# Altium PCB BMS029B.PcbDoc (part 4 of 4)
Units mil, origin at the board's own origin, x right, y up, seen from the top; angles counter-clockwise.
Board outline 4950 x 4000 mil, 4 copper layers (Layer 1 - Top Layer, Layer 2 - GND, Layer 3 - Signal, Layer 4 - Bottom Layer), stack 61.4 mil thick; 370 components, 202 nets, 969 pads, 408 vias.
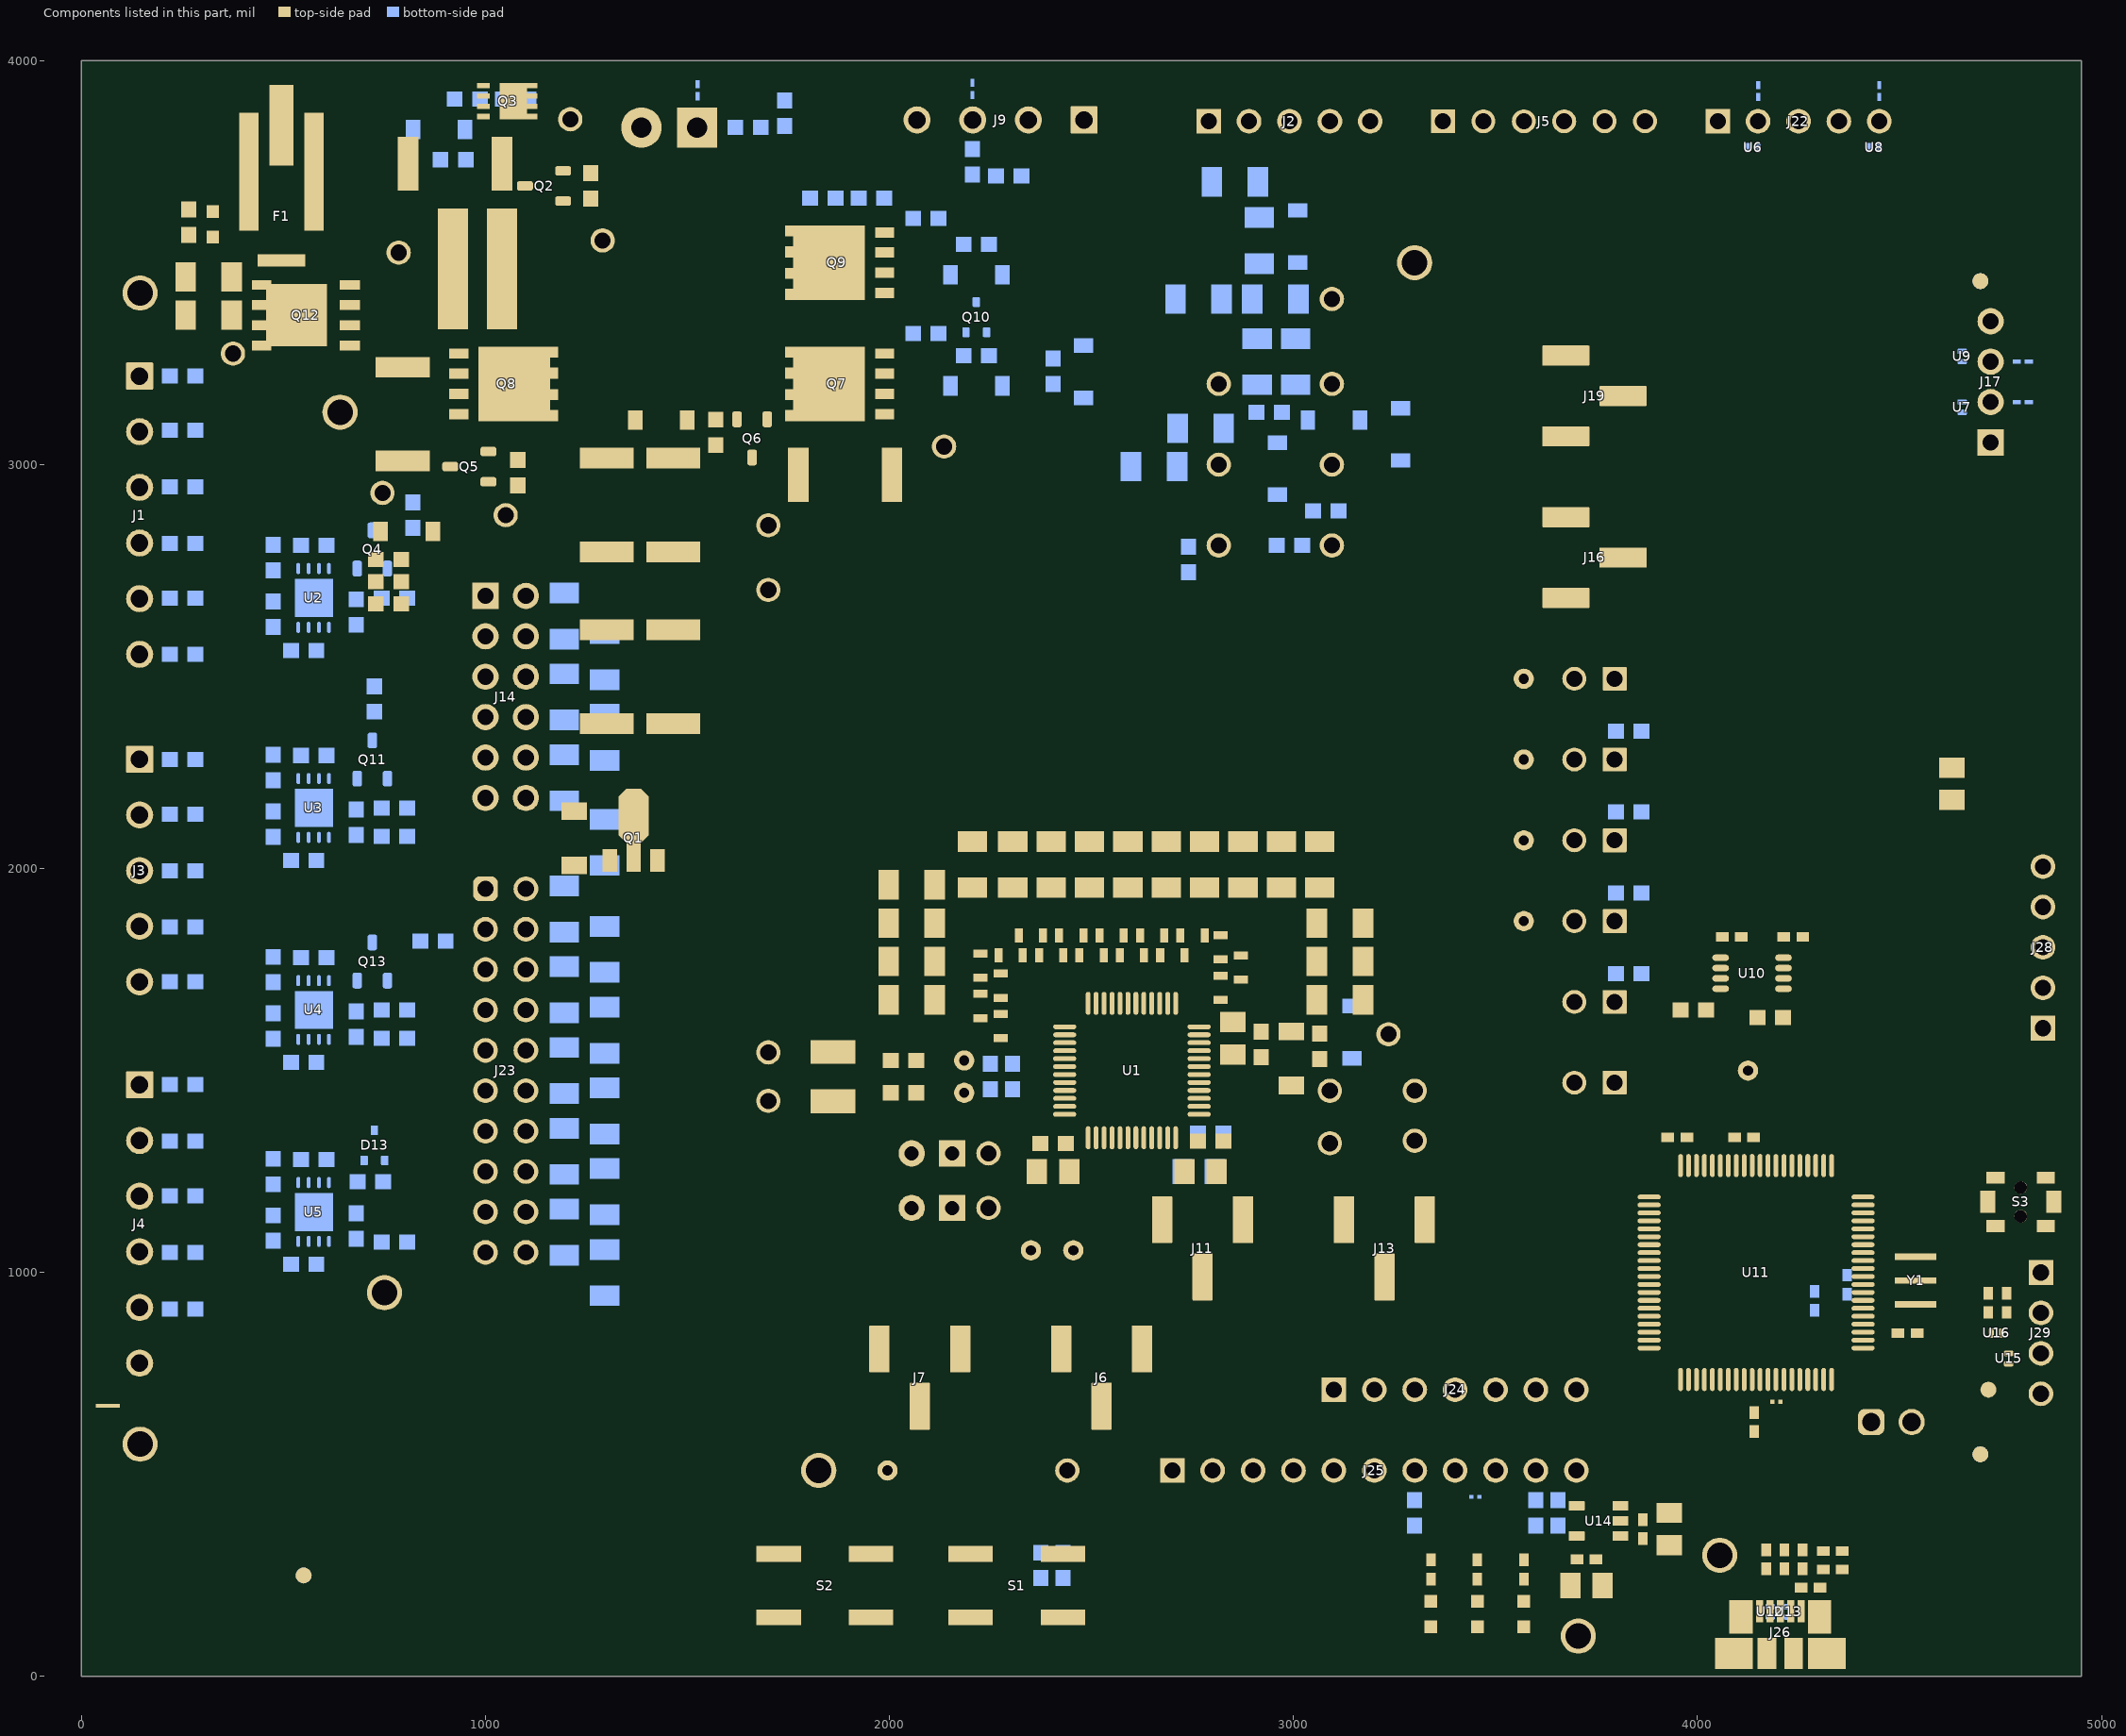
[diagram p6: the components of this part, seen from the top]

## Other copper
Layer 1 - Top Layer:
  pour cut-out: 1435,1924.51 1435.49,1925 1475,1925 1475,1935 1435,1935
  region net NetF1_2: 505,3580 610,3475 610,3285 565,3240 350,3240 305,3285 305,3395 320,3410 400,3410 415,3425 415,3530 440,3555 460,3555 485,3580
  region net NetQ5_3: 950,2960 935,2945 820,2945 785,2980 725,2980 710,2995 710,3070 730,3090 845,3090 865,3070 865,3045 885,3025 935,3025 950,3010
  region net NetD2_1: 1405,3135 1475,3065 1515,3065 1535,3045 1535,2905 1510,2880 1230,2880 1205,2905 1205,3065 1275,3135
  region net CD: 980,3605 980,3080 980,2986 1093.5,2986 1133.37,3025.87 1168.75,3061.25 1177.5,3070 1262.5,3155 1410,3155 1480,3085 1645,3085 1660,3100 1660,3135 1680,3155 1715,3155 1735,3135 1735,3100 1745,3090 1925,3090 1940,3105 1940,3600 1935,3605 1110,3605 1080,3635 1000,3635 980,3615
  region net NetC71_1: 1210,2465 1180,2435 1180,2100 1210,2070 1330,2070 1345,2055 1345,1990 1390,1990 1390,2055 1405.01,2070.01 1425.01,2070.01 1470,2115 1470,2210 1585,2325 1585,2435 1555,2465
  region net NetR6_1: 1370,2515 1340,2485 1210,2485 1180,2515 1180,2830 1210,2860 1370,2860
  region net NetR5_1: 1395,2515 1425,2485 1555,2485 1585,2515 1585,2830 1555,2860 1395,2860
  pour cut-out: 694.71,3070 694.71,3225 705,3225 715,3215 715,3085 700,3070
  region net QGND: 4027,1711 4081.82,1711 4085,1707.82 4085,1702 4027,1702
  region net PGND: 4610,2232 4603,2225 4577.42,2225 4577.42,2260 4682.58,2260 4682.58,2225 4655,2225 4648,2232
  region net QGND: 4610,2188 4603,2195 4577.42,2195 4577.42,2160 4682.58,2160 4682.58,2195 4655,2195 4648,2188
  pour cut-out: 4899.65,1085.2 4899.65,1264.8 4700.35,1264.8 4700.35,1085.2
  pour cut-out: 3054.49,755.51 3054.49,845 3085,845 3085,755.51
  pour cut-out: 3731.81,372.81 3731.81,386.81 3743,398 3783,398 3783,409 3726,409 3720,403 3720,372.81
  pour cut-out: 4675,3105 4675,3405 4775,3405 4775,3105
  pour cut-out: 3825,700 4475,700 4475,1325 3825,1325
  pour cut-out: 2650,460 3745,460 3745,560 2650,560
  pour cut-out: 2035,510 2050,510 2160,620 2160,825 2085,825 2085,600 2035,550
  pour cut-out: 2425,1325 2775,1325 2775,1675 2425,1675
  pour cut-out: 3131.5,1912.32 3098.5,1912.32 3098.5,1621.95 3131.5,1621.74
  pour cut-out: 2153.58,2026.5 2153.58,1993.5 3116.42,1993.5 3116.42,2026.5
  pour cut-out: 2038.5,1623.58 2071.5,1623.58 2071.5,2011.42 2038.5,2011.42
  pour cut-out: 950,2125 1150,2125 1150,2725 950,2725
  region net VSS: 55,690 45,700 20,700 20,640 45,640 55,650
  region net VSS: 690,3410 690,3115 660,3085 620,3085 590,3115 590,3235 635,3280 635,3410
  region net QGND: 4600,2185 4590,2175 4590,2125 4670,2125 4670,2175 4660,2185
  region net PGND: 4660,2235 4670,2245 4670,2295 4590,2295 4590,2245 4600,2235
  region net VSS: 2785,1215 2865,1215 2890,1240 2890,1305 2850,1345 2805,1345 2805,1305 2785,1285
  region net VSS: 2900,1555 2900,1490 2950,1440 3030,1440 3030,1490 2965,1555
  region net BAT-: 75,475 135,415 1550,415 1920,785 1920,1420 1940,1440 1940,1450 1920,1470 1649.99,1469.99 1500,1320 1500,965 1370,835 150,835 75,760
  region net PGND: 1920,1500 1940,1520 1940,1530 1920,1550 1920,2020 2705,2805 2705,3850 2630,3925 2360,3925 2285,3850 2285,2980 1500,2195 1500,1650 1650,1500
  region net 16P: 60,3145 30,3175 30,3625 30,3940 60,3970 455,3970 485,3940 485,3718.75 485,3610 450,3575 390,3575 355,3610 340,3610 240,3610 215,3585 215,3330 300,3245 300,3175 270,3145
  region net FBAT: 505,3940 535,3970 990,3970 1015,3945 1015,3885 1009,3879 969,3879 960,3870 960,3160 955,3155 780,3155 710,3225 710,3485 690,3505 610,3505 505,3610
  region net NetQ2_3: 1000,3675 1125,3675 1125,3820 1110,3835 1085,3835 1035,3835 980,3780 980,3695
  region net CPACK+: 1035,3875 1035,3855 1130,3855 1158,3827 1158,3700 1290,3700 1350,3640 1725,3640 1760,3675 1760,3890 1725,3925 1470,3925 1425,3970 1060,3970 1035,3945
  region net NetQ6_3: 1645,2985 1735,2895 1860,2895 1880,2915 1880,3025 1862,3043 1645,3043
  region net PACK+: 2265,3850 2265,2990 2170,2895 1920,2895 1900,2915 1900,3040 1960,3100 1960,3235 1965,3240 2020,3240 2035,3255 2035,3305 2005,3335 1975,3335 1960,3350 1960,3535 1965,3540 2020,3540 2035,3555 2035,3615 2010,3640 1943.5,3640 1900,3683.5 1900,3830 1900,3875 1950,3925 2190,3925
  region net 12P: 100,2650 145,2605 355,2605 770.89,2189.11 770.89,2075 795,2050.89 834.11,2050.89 858.23,2075 858.23,2343.23 651.46,2550 651.46,2650 651.46,2688.54 610,2730 145,2730 100,2685
  region net VSS: 770,2688.7 848.7,2688.7 915,2755 915,2875 860,2875 770,2785
  region net 8P: 560,1930 770,1720 770,1580 795,1555 835,1555 860,1580 860,1920 730,2050 730,2160 690,2200 490,2200 349.45,2059.45 139.45,2059.45 100,2020 100,1970 140,1930
  region net 4P: 140,1390 190,1390 500,1700 625,1700 725,1600 725,1495 860,1360 860,1075 835,1050 795,1050 770,1075 770,1179.37 679.37,1270 135,1270 100,1305 100,1350
  region net QGND: 4488,996 4491,999 4593,999 4601,1007 4617,1007 4617,953 4601,953 4593,961 4491,961 4488,964
  region net VBUS: 4162,134.13 4162,223.64 4135.51,250.13 4135.51,315.13 4090.51,360.13 3790.51,360.13 3785.51,355.13 3785.51,319.49 3894.87,210.13 4134.51,210.13 4145,199.64 4145,134.13
  region net NetJ26_6: 4137,190 4137,106 4147,96 4262,96 4273,107 4273,193 4285,205 4285,230 4290,235 4329.21,235 4370,194.21 4370,18 4043,18 4043,163 4070,190
  region net QGND: 3810,185 3746.46,185 3732,199.46 3732,382 3748,398 3838,398 3845,405 3845,440 3865,460 3955,460 3965,450 3965,380 3957,372 3787,372 3775,360 3775,310 3826,259 3826,201 3825,200
  region net 3.3V: 3721,164 3755,130 3755,80 3720,45 3630,45 3605,70 3605,256.65 3591.65,270 3315,270 3300,285 3300,360 3315,375 3708,375 3721,362
  region net QGND: 4700,700 4720,680 4765,680 4765,730 4700,730
  pour cut-out: 3370.75,92.76 3539.25,92.76 3539.25,100 3370.75,100
  text ".Layer_Name" at 577,-858.49 h60
Layer 2 - GND:
  pour cut-out: 2206.11,3804.68 2270,3804.68 2270,3815 2206.11,3815
  pour cut-out: 2120,3419.51 2180,3419.51 2180,3430 2120,3430
  pour cut-out: 1595,3765 1320,3765 1320,3900 1595,3900
  pour cut-out: 4380,580 4580,580 4580,680 4380,680
  pour cut-out: 4675,3105 4675,3405 4775,3405 4775,3105
  pour cut-out: 950,2125 1150,2125 1150,2725 950,2725
  text ".Layer_Name" at 577,-858.49 h60
Layer 3 - Signal:
  pour cut-out: 3750.14,1447.55 3750,1405 3760,1405 3760,1447.55
  pour cut-out: 935,2725 935,2125 1150,2125 1150,2725
  pour cut-out: 955,1000 955,2000 1210,2000 1210,1000
  pour cut-out: 1590,3765 1320,3765 1320,3900 1590,3900
  pour cut-out: 2206.11,3804.68 2270,3804.68 2270,3815 2206.11,3815
  pour cut-out: 2120,3419.51 2180,3419.51 2180,3430 2120,3430
  pour cut-out: 2305,2084.51 3160,2084.51 3160,2110 2305,2110
  pour cut-out: 4380,580 4580,580 4580,680 4380,680
  pour cut-out: 4895.9,800 4895.9,900 4804.1,900 4804.1,800
  pour cut-out: 4768.99,1139.57 4768.99,1210.43 4790,1210.43 4790,1139.57
  pour cut-out: 4675,3105 4675,3405 4775,3405 4775,3105
  text ".Layer_Name" at 577,-858.49 h60
Layer 4 - Bottom Layer:
  pour cut-out: 4396.81,915.63 4396.81,901.81 4380,885 4357.5,885 4357.5,915.63
  pour cut-out: 3184.02,1497.52 3187.91,1497.52 3240.49,1550.1 3240.49,1675 3230.49,1685 3223.01,1692.48 3105.98,1692.48 3105.98,1559.98 3074.51,1528.5 3074.51,1425.49 3100,1400 3150,1400 3184.02,1434.02
  pour cut-out: 2546.5,286.1 2615,286.1 2615,300 2546.5,300
  pour cut-out: 2450.39,400 2450.39,480 2430,480 2430,400
  pour cut-out: 2857.32,3148.58 3052.68,3148.58 3052.68,3180 2857.32,3180
  pour cut-out: 1296.42,647.32 1296.42,2443.58 1265,2475 1125,2475 1100,2450 1100,2386.5 1004.1,2290.59 1004.1,795 1050,749.1 1193.58,749.1 1193.58,647.32
  pour cut-out: 316.18,1291.3 316.18,1083 304.34,1083 300,1083 300,1291.3
  pour cut-out: 316.18,1961.3 316.18,1753.7 300,1753.7 300,1961.3
  pour cut-out: 316.18,2636.3 316.18,2563.7 299,2563.7 299,2636.3
  pour cut-out: 316.18,2563.7 316.18,2636.3 301.89,2636.3 301.89,2563.7
  pour cut-out: 316.18,3186.3 316.18,2978.7 293,2978.7 293,3186.3
  pour cut-out: 1320.69,3834.5 1320.69,3753 1333,3753 1333,3834.5
  pour cut-out: 3240,3800 3254.51,3800 3254.51,3808 3240,3808
  region net PGND: 4132,3806.67 4129.4,3809.27 4126.27,3809.27 4125,3808 4125,3762 4126,3761 4129,3761 4132,3764
  region net PGND: 4432,3806.67 4429.4,3809.27 4426.27,3809.27 4425,3808 4425,3762 4426,3761 4429,3761 4432,3764
  region net PGND: 4675,3273 4675,3284 4636,3284 4630,3278 4630,3276 4633,3273
  region net PGND: 4675,3137 4675,3125 4637,3125 4630,3132 4630,3134 4633,3137
  pour cut-out: 4900.9,1559.49 4884,1559.49 4884,1905 4900.9,1905
  region net QGND: 4157,164 4250,164 4250,172 4157,172
  pour cut-out: 2654.49,464.1 2654.49,555.9 3735,555.9 3735,464.1
  pour cut-out: 950,2125 1150,2125 1150,2725 950,2725
  region net VSS: 2780,1285 2890,1285 2890,1240 2875,1225 2840,1225 2830,1215 2780,1215
  region net PGND: 4435,3900 4420,3900 4405,3915 4405,3965 4495,3965 4495,3915 4480,3900 4465,3900 4465,3925 4460,3930 4440,3930 4435,3925
  region net PGND: 4135,3900 4120,3900 4105,3915 4105,3965 4195,3965 4195,3915 4180,3900 4165,3900 4165,3925 4160,3930 4140,3930 4135,3925
  region net PGND: 4780,3130 4795,3115 4865,3115 4865,3295 4795,3295 4780,3280 4780,3270 4805,3270 4810,3265 4810,3245 4805,3240 4780,3240 4780,3170 4805,3170 4810,3165 4810,3145 4805,3140 4780,3140
  region net FBAT: 950,3890 945,3885 920,3885 910,3875 910,3735 798.03,3735 798.03,3928.03 815,3945 935,3945 950,3930
  region net NetC29_1: 965,3885 1065,3885 1065,3930 1050,3945 980,3945 965,3930
  region net CPACK+: 1085,3880 1100,3865 1155,3865 1155,3945 1100,3945 1085,3930
  region net CPACK+: 1640,3800 1620,3780 1475,3780 1465,3790 1465,3875 1475,3885 1515,3885 1520,3890 1520,3922 1530,3922 1530,3890 1535,3885 1620,3885 1640,3865
  region net NetC34_2: 1660,3810 1670,3800 1755,3800 1765,3810 1765,3855 1755,3865 1670,3865 1660,3855
  region net PGND: 1700,3965 1700,3900 1720,3880 1760,3880 1780,3900 1780,3965
  region net PACK+: 2195,3575 2205,3565 2205,3455 2185,3435 2110,3435 2110,3555 2130,3575
  region net PACK+: 1965,3640 2020,3640 2035,3655 2035,3735 1980,3735 1965,3720
  region net PGND: 1510,3902 1495,3902 1480,3917 1480,3967 1570,3967 1570,3917 1555,3902 1540,3902 1540,3927 1535,3932 1515,3932 1510,3927
  region net PGND: 2190,3905 2175,3905 2160,3920 2160,3970 2250,3970 2250,3920 2235,3905 2220,3905 2220,3930 2215,3935 2195,3935 2190,3930
  region net PACK+: 2200,3925 2200,3900 2170,3870 2170,3760 2240,3760 2240,3870 2210,3900 2210,3925
  region net NetC42_2: 2185,3740 2185,3690 2285,3690 2285,3740
  region net PGND: 2305,3690 2320,3675 2370,3675 2370,3755 2320,3755 2305,3740
  region net PGND: 2450,3125 2530,3125 2530,3205 2450,3205
  region net 12P: 527,2718 527,2622 627,2622 650,2645 765,2645 765,2690 650,2690 622,2718
  region net 8P: 527,2198 527,2102 627,2102 650,2125 765,2125 765,2170 650,2170 622,2198
  region net 4P: 527,1698 527,1602 627,1602 650,1625 765,1625 765,1670 650,1670 622,1698
  region net VSS: 527,1198 527,1102 627,1102 650,1125 700,1125 700,1170 650,1170 622,1198
  pour cut-out: 4245,343.45 4245,365 4230,380 4230,795 4250,815 4325,815 4345,795 4370,795 4385,810 4385,890 4370,905 4345,905 4286,846 4236,846 4200,810 4200,415 4140,355 4140,335 4155,320 4230,320 4245,335
  region net NetC37_1: 1845,3630 1945,3630 1945,3700 1845,3700
  region net FBAT: 1825,3630 1320,3630 1265,3685 1190,3685 1110,3605 890,3605 880,3615 880,3670 890,3680 1065,3680 1155,3770 1300,3770 1370,3700 1815,3700 1825,3690
  pour cut-out: 4675,3105 4675,3405 4775,3405 4775,3105
  region net PACK+: 2205,3065 2235,3035 2625,3035 2635,3025 2635,2960 2625,2950 2200,2950 2175,2950 2115,3010 2095,3030 2095,3230 2165,3300 2165,3340 2175,3350 2195,3350 2205,3340
  region net CD: 1940,3605 1295,3605 1090,3400 1090,3014.75 1122.25,3014.75 1262.5,3155 1420,3155 1450,3125 1940,3125
  pour cut-out: 2625,3050.29 2679.71,3050.29 2680.01,2920 2625,2920
  pour cut-out: 2753.5,3038.58 2795,3038.58 2795,3141.42 2753.5,3141.42
  pour cut-out: 3056.42,3238.5 3056.42,3280 2858.58,3280 2858.58,3238.5
  pour cut-out: 2748.5,3358.58 2790,3358.58 2790,3461.42 2748.5,3461.42
  pour cut-out: 2966.42,3538.5 2966.42,3580 2863.58,3580 2863.58,3538.5
  pour cut-out: 2838.5,3648.58 2880,3648.58 2880,3751.42 2838.5,3751.42
  text ".Layer_Name" at 577,-858.49 h60

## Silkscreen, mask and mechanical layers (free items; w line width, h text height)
Top Overlay:
  text "EXT SPI" at 4115,3920 h75
  text "CPACK+" at 1115,3780 h50
  text "CPACK+" at 1320,3660 h75
  text "TS2" at 3215,3655 h75 r90
  text "PACK+" at 2031.01,3644.5 h75
  text "PACK-" at 2314.71,3644.5 h75
  text "VSS" at 2815,3640 h75 r90
  text "VSS" at 3395,3640 h75 r90
  text "REG1" at 3015,3605 h75 r90
  text "REG2" at 2915,3595 h75 r90
  text "DCHG" at 3695,3585 h75 r90
  text "DDSG" at 3795,3585 h75 r90
  text "Input 6A max" at 2055,3580 h75
  text "REGIN" at 3115,3570 h75 r90
  text "PACK-" at 4075,3565 h75 r90
  text "SPI_CS" at 4175,3540 h75 r90
  text "BAT+" at 45,3510 h75
  text "SPI_CLK" at 4275,3495 h75 r90
  text "DFETOFF" at 3495,3470 h75 r90
  text "CFETOFF" at 3595,3470 h75 r90
  text "SPI_MISO" at 4375,3465 h75 r90
  text "SPI_MOSI" at 4475,3465 h75 r90
  text "FBAT" at 730,3450 h50
  text "CD" at 1260,3435 h50
  text "RST_SHUT" at 3895,3425 h75 r90
  text "GND" at 3230,3320 h75
  text "PACK" at 3035,3290 h50
  text "uC_SCL" at 3865,3245 h75
  text "FUSE" at 405,3220 h50
  text "CELL16" at 316.06,3160 h75
  text "SCL" at 3500,3140 h75
  text "Dg" at 2788.25,3089.94 h50
  text "DSG" at 3050,3090 h50
  text "EXT I2C" at 4660,3080 h75 r90
  text "CELL15" at 316.06,3057.65 h75
  text "uC_SPI_CLK" at 3865,3045 h75
  text "GND" at 570,3000 h75
  text "CELL14" at 316.06,2919.65 h75
  text "PACK+" at 2070,2915 h50
  text "FUSEPIN" at 785,2890 h50
  text "LD" at 2790,2890 h50
  text "PCHG" at 3035,2890 h50
  text "uC_SDA" at 3865,2845 h75
  text "CELL13" at 316.06,2781.65 h75
  text "Pcg" at 1010,2760 h50
  text "SDA" at 3500,2745 h75
  text "Pdg" at 1660,2740 h50
  text "CHG" at 2775,2690 h50
  text "PDSG" at 3040,2690 h50
  text "16" at 860,2650 h75
  text "uC_SPI_MISO_A" at 3865,2645 h75
  text "CELL12" at 316.06,2643.65 h75
  text "Cg" at 1670,2575 h50
  text "15" at 860,2550 h75
  text "CELL11" at 316.06,2505.65 h75
  text "14" at 860,2450 h75
  text "CFETOFF" at 3325,2440 h50
  text "uC_SPI_CS" at 3570,2355 h75
  text "13" at 860,2350 h75
  text "12" at 860,2250 h75
  text "CELL10" at 316.06,2246.65 h75
  text "HDQ" at 3425,2225 h50
  text "Cell simulator" at 1210,2205 h75 r90
  text "HDQ_PU" at 3620,2155 h75
  text "11" at 860,2150 h75
  text "CELL9" at 316.06,2108.65 h75
  text "SDA" at 3435,2030 h50
  text "CELL8" at 316.06,1970.65 h75
  text "SDA_PU" at 3620,1955 h75
  text "10" at 860,1925 h75
  text "SCL" at 3435,1835 h50
  text "CELL7" at 316.06,1832.65 h75
  text "9" at 895,1825 h75
  text "SCL_PU" at 3620,1755 h75
  text "8" at 895,1725 h75
  text "CELL6" at 316.06,1694.65 h75
  text "7" at 895,1625 h75
  text "ALERT_PU" at 3580,1555 h75
  text "BAT" at 3275,1545 h50
  text "6" at 895,1525 h75
  text "SRN" at 2225,1510 h50
  text "CELL5" at 316.06,1435.65 h75
  text "SRP" at 2225,1430 h50
  text "5" at 895,1425 h75
  text "CP1" at 3135,1405 h50
  text "GND" at 3340,1405 h50
  text "BAT-" at 1510,1375 h75
  text "uC_HDQ" at 3610,1355 h75
  text "TS1" at 2205,1335 h50
  text "4" at 895,1325 h75
  text "Input 72V max" at 715,1310 h75 r90
  text "Input 6A max" at 800,1310 h75 r90
  text "CELL4" at 316.06,1297.65 h75
  text "BREG" at 3135,1280 h50
  text "REGIN" at 3340,1280 h50
  text "Cell simulator" at 1210,1265 h75 r90
  text "3" at 895,1225 h75
  text "CELL3" at 316.06,1159.65 h75
  text "2" at 895,1125 h75
  text "ALERT" at 2405,1090 h50
  text "PU" at 2610,1080 h75 r90
  text "PD" at 2990,1080 h75 r90
  text "TS3" at 2205,1040 h50
  text "1" at 900,1025 h75
  text "CELL2" at 316.06,1021.65 h75
  text "uC_HDQ" at 3440,980 h75 r90
  text "REG18" at 2275,945 h50
  text "CELL1" at 316.06,883.65 h75
  text "uC_SPI_MOSI" at 3050,855 h75 r90
  text "GND" at 675,775 h75
  text "HDQ" at 3250,775 h75 r90
  text "PD" at 2290,760 h75 r90
  text "PU" at 2360,760 h75 r90
  text "PD" at 2740,760 h75 r90
  text "EXT" at 1905,755 h75 r90
  text "BAT-" at 316.06,745.65 h75
  text "QGND" at 4595,625 h75
  text "CFETOFF" at 2800,615 h75 r90
  text "TS2" at 2100,475 h75 r90
  text "TS2" at 1955,400 h50
  text "REG1" at 2365,390 h50
  text "VBUS" at 3980,385 h75
  text "GND" at 1755,370 h75
  text "DFETOFF" at 2550,295 h75 r90
  text "BQ76952EVM" at 745,215 h108.27
  text "'.PRJ_Number'.PCB_Rev" at 745,125 h108.27
  text "USB" at 4405,80 h75
  text "3.3V" at 3795,60 h75
  text "WAKE" at 1740,30 h75
  text "RESET" at 2210,30 h75
  text ".Layer_Name" at 577,-858.49 h60
Bottom Overlay:
  text ".Layer_Name" at 577,-858.49 h60
Top Paste:
  text ".Layer_Name" at 577,-858.49 h60
Bottom Paste:
  text ".Layer_Name" at 577,-858.49 h60
Top Solder:
  text ".Layer_Name" at 577,-858.49 h60
  text ".Layer_Name" at 577,-858.49 h60
Bottom Solder:
  text ".Layer_Name" at 577,-858.49 h60
Drill Guide:
  text ".Layer_Name" at 577,-858.49 h60
M1 Board Outline:
  the board outline again, w10
  text ".Layer_Name" at 577,-858.49 h60
M2 Board Dimensions:
  rectangle: 0,-275 125,-150
  rectangle: 125,-400 500,-275
  lines w7: 0,-275 1000,-275 ; 125,-400 125,-150 ; 250,-400 250,-150 ; 500,-400 500,-150 ; 750,-400 750,-150 ; 0,-400 1000,-400 1000,-150 0,-150 0,-400
  text ".Layer_Name" at 577,-858.49 h60
M3 3D STEP Top:
  text ".Layer_Name" at 577,-858.49 h60
M4 3D STEP Bottom:
  text ".Layer_Name" at 577,-858.49 h60
M5 Assembly Top:
  lines w10: -292,-930.17 6308,-930.17 ; -292,-726.83 6310,-726.83 ; -292,-523.5 -292,-1133.5 3713,-1133.5 6310,-1133.5 6310,-523.5 -291.5,-523.5 -291.5,-1133.5 1284,-1133.5 ; 2173,-1133.5 2173,-523.5 ; 3440,-726.83 3440,-523.5 ; 4280,-726.83 4280,-523.5 ; 4902,-1140 4902,-937.17
  text "COMPONENTS MARKED 'DNP' SHOULD NOT BE POPULATED." at 1153.5,-318.5 h60
  text "ASSEMBLY VARIANT:" at 1153,-434 h60
  text ".VariantName" at 2189,-434 h60
  text "PCB VIEWED FROM TOP SIDE" at -228.5,-655.67 h60
  text "BOARD #:" at 2248,-655.67 h60
  text ".PRJ_Number" at 2793.5,-655.67 h60
  text "REV:" at 3638,-655.67 h60
  text ".PCB_Rev" at 3929.5,-655.67 h60
  text "SVN REV:" at 4476,-655.67 h60
  text ".VersionControl_RevNumber" at 4982,-655.67 h60
  text "TID #:" at 2248,-859 h60
  text ".TID" at 2793.5,-859 h60
  text "PLOT NAME =" at -228.5,-1064.34 h60
  text ".plot_File_Name" at 577,-1064.34 h60
  text "GENERATED    :" at 2250,-1064.34 h60
  text ".Print_Date" at 3119.5,-1064.34 h60
  text ".Print_Time" at 3848.5,-1064.34 h60
  text "TEXAS INSTRUMENTS" at 5113,-1064.34 h60
M6 Assembly Bottom:
  lines w10: -292.5,-727.33 6309.5,-727.33 ; -290.5,-930.67 6309.5,-930.67 ; 1115.5,-1140.5 1115.5,-937.67 ; 1737.5,-727.33 1737.5,-524 ; 2577.5,-727.33 2577.5,-524 ; 3844.5,-1134 3844.5,-524 ; 4733.5,-1134 6309,-1134 6309,-524 -292.5,-524 -292.5,-1134 2304.5,-1134 6309.5,-1134 6309.5,-524
  text "COMPONENTS MARKED 'DNP' SHOULD NOT BE POPULATED." at 6102,-318 h60
  text ".VariantName" at 5058,-434 h60
  text "ASSEMBLY VARIANT:" at 6097,-434 h60
  text ".VersionControl_RevNumber" at 1035.5,-656.17 h60
  text "SVN REV:" at 1541.5,-656.17 h60
  text ".PCB_Rev" at 2088,-656.17 h60
  text "REV:" at 2379.5,-656.17 h60
  text ".PRJ_Number" at 3224,-656.17 h60
  text "BOARD #:" at 3769.5,-656.17 h60
  text "PCB VIEWED FROM BOTTOM SIDE" at 6246,-656.17 h60
  text ".TID" at 3224,-859.5 h60
  text "TID #:" at 3769.5,-859.5 h60
  text "TEXAS INSTRUMENTS" at 904.5,-1064.84 h60
  text ".Print_Time" at 2169,-1064.84 h60
  text ".Print_Date" at 2898,-1064.84 h60
  text "GENERATED    :" at 3767.5,-1064.84 h60
  text ".plot_File_Name" at 5440.5,-1064.84 h60
  text "PLOT NAME =" at 6246,-1064.84 h60
M9 Title Sheet:
  drawing of 1178 lines, arcs and shapes, not listed
  text "1" at 739.84,8036.5 h70
  text "2" at 3235.5,8036.5 h70
  text "3" at 5724.84,8036.5 h70
  text "4" at 8231.51,8036.5 h70
  text "5" at 10730.5,8036.5 h70
  text "6" at 13235.5,8036.5 h70
  text "A" at -416.5,6893.5 h70
  text "A" at 14383.5,6893.5 h70
  text "B" at -416.5,4513.5 h70
  text "B" at 14383.5,4513.5 h70
  text "C" at -416.5,2138.5 h70
  text "C" at 14383.5,2138.5 h70
  text "PROJECT TITLE:" at 11343.5,277.5 h45
  text ".PRJ_Title" at 11393.5,144.17 h70
  text "DESIGNED FOR:" at 11343.5,-23.5 h45
  text ".PRJ_Customer" at 11393.5,-163.5 h70
  text "D" at -416.5,-231.5 h70
  text "D" at 14383.5,-231.5 h70
  text "FILE NAME:" at 11343.5,-323.5 h45
  text ".PCB_File_Name_No_Path" at 11393.5,-443.5 h70
  text "Texas Instruments (TI) and/or its licensors do not warrant the accuracy or completeness of this specification" at 6374,-605.34 h45
  text "ENGINEER:" at 11343.5,-613.5 h45
  text "LAYOUT BY:" at 12848.5,-613.5 h45
  text "or any information contained therein. TI and/or its licensors do not warrant that this design will meet" at 6329.01,-718 h45
  text ".PRJ_Engineer" at 11393.5,-768.49 h70
  text "JMM" at 12852,-800 h100
  text "s  o  l  u  t  i  o  n  s" at 13710,-803 h68
  text "the specifications, will be suitable for your application or fit for any particular purpose, or will operate in" at 6329.01,-830.67 h45
  text ".Layer_Name" at 577,-858.49 h60
  text "ALTIUM DESIGNER VERSION:" at 12848.5,-923.5 h45
  text "an implementation. TI and/or its licensors do not warrant that the design is production worthy. You should" at 6329.01,-943.33 h45
  text "completely validate and test your design implementation to confirm the system functionality for your application." at 6374,-1056 h45
  text ".print_Scale" at 11393.5,-1056.83 h70
  text ".Application_BuildNumber" at 12899,-1056.83 h70
  text "1" at 739.84,-1263.5 h70
  text "2" at 3235.5,-1263.5 h70
  text "3" at 5724.84,-1263.5 h70
  text "4" at 8231.51,-1263.5 h70
  text "5" at 10730.5,-1263.5 h70
  text "6" at 13235.5,-1263.5 h70
M10 Fab Notes:
  drawing of 189 lines, arcs and shapes, not listed
  text "DESIGN INFORMATION" at 12382.02,6356.17 h60
  text "MIN. TRACK WIDTH:" at 11737.46,6224.05 h60
  text "8" at 12833.7,6224.05 h60
  text "MIL" at 12988.46,6224.05 h60
  text "MIN. CLEARANCE:" at 11737.46,6099.92 h60
  text "0.2" at 12773.7,6099.93 h60
  text "mm" at 12988.46,6099.92 h60
  text "MIN. VIA PAD SIZE:" at 11737.46,5975.8 h60
  text "20" at 12803.71,5975.8 h60
  text "MIL" at 12988.46,5975.8 h60
  text "0.05mm (2MIL)" at 12432.46,5845.9 h60
  text "MINIMUM ANNULAR RING" at 11408.23,5837.67 h60
  text "EXTERNAL" at 13140.46,5837.67 h60
  text "PER" at 11608.23,5727.55 h60
  text "IPC-D-275 CLASS 2 LEVEL C" at 11828.23,5727.54 h60
  text "MIL, HOLES" at 13316.46,5627.07 h60
  text "+/-" at 12924,5618.48 h60
  text "+/-" at 13778,5618.48 h60
  text "REGISTRATION TOLERANCES:" at 11408.23,5617.42 h60
  text "METAL" at 12608,5617.42 h60
  text "5" at 13184.2,5617.42 h60
  text "3" at 14017.2,5617.42 h60
  text "MIL" at 14133.46,5617.42 h60
  text "HOLE SIZE TOLERANCE (UNLESS OTHERWISE SPECIFIED):" at 11408.23,5519.1 h60
  text "+/-" at 13778,5516.23 h60
  text "3" at 14017.2,5515.17 h60
  text "MIL" at 14133.46,5515.17 h60
  text "MATERIAL:" at 11333.46,5377.52 h60
  text "FR-4 High Tg" at 12319.9,5249 h60
  text "X" at 12175.46,5241.01 h60
  text "FR-408" at 11754.46,5236.49 h60
  text "OTHER" at 13242.46,5236.49 h60
  text "62 MIL (1.6mm) +/-10%" at 12074.56,5093.46 h60
  text "X" at 11954.46,5091.01 h60
  text "THICKNESS:" at 11408.23,5085.24 h60
  text "OTHER" at 13359.46,5085.24 h60
  text "TOLERANCE:" at 11408.23,4946.92 h60
  text "X" at 12256.46,4946.92 h60
  text "ANSI IPC-6012 TYPE 3 CLASS 2" at 12434.48,4946.92 h60
  text "OTHER +/-" at 12434.46,4802.73 h60
  text "BOW & TWIST:" at 11408.23,4657.54 h60
  text "X" at 12256.46,4657.54 h60
  text "ANSI IPC-6012 TYPE 3 CLASS 2" at 12434.48,4657.54 h60
  text "OTHER +/-" at 12434.46,4510.85 h60
  text "DRILLING:" at 11333.46,4380.23 h60
  text "NC_DRILL FILES" at 13094.46,4275.04 h60
  text "REFERENCE:" at 11408.23,4271.1 h60
  text "X" at 12065.46,4271.01 h60
  text "AS SHOWN" at 12243.46,4271.1 h60
  text "X" at 12966.46,4271.1 h60
  text "OTHER" at 13392.46,4128.85 h60
  text "PTH COPPER THICKNESS:" at 11407.91,4125.32 h60
  text "X" at 12547.14,4125.32 h60
  text "20-30 um" at 12675.14,4125.32 h60
  text "BOARD FINISH:" at 11333.46,3977.73 h60
  text "SILKSCREEN:" at 11488.68,3867.6 h60
  text "X" at 12446.46,3867.6 h60
  text "TOP" at 12563.46,3867.6 h60
  text "X" at 12956.46,3867.6 h60
  text "BOTTOM" at 13074.46,3867.6 h60
  text "SILKSCREEN COLOR:" at 11488.68,3712.41 h60
  text "X" at 12445.46,3712.41 h60
  text "WHITE" at 12563.46,3712.41 h60
  text "OTHER" at 13074.46,3712.41 h60
  text "X" at 12576.46,3568.96 h60
  text "GREEN" at 12694.46,3568.96 h60
  text "OTHER" at 13312.46,3568.96 h60
  text "SOLDER RESIST COLOR:" at 11488.68,3562.1 h60
  text "X" at 12576.46,3414.71 h60
  text "MATTE" at 12694.46,3414.71 h60
  text "SEMI-GLOSS" at 13312,3414.07 h60
  text "IMMERSION GOLD (ENIG)" at 12394.46,3241.94 h60
  text "ENEPIG" at 13732,3234.72 h60
  text "SURFACE FINISH:" at 11333.46,3233.72 h60
  text "X" at 12216.46,3233.72 h60
  text "IMM. TIN/SILVER OR EQUIV" at 11663,3096.4 h60
  text "OTHER" at 13094.46,3092.47 h60
  text "ARRAY/PANEL:" at 11333.46,2937.09 h60
  text "CUT AND TRIM PER M1 BOARD OUTLINE" at 12394.46,2928.87 h60
  text "N.C. ROUTE" at 12394.46,2792.9 h60
  text "X" at 13082.46,2792.9 h60
  text "V. SCORE" at 13260.46,2792.9 h60
  text "CERTIFICATION:" at 11333.46,2663.77 h60
  text "MATERIALS AND WORKMANSHIP FOR ALL PCBS" at 12058.46,2663.77 h60
  text "TO MEET OR EXCEED THE REQUIREMENTS OF:" at 12058.46,2569.71 h60
  text "X" at 11695.97,2441.08 h60
  text "ANSI IPC-A-600F CLASS ->" at 11823.96,2441.08 h60
  text "X" at 13471.97,2441.08 h60
  text "2" at 13581.96,2441.08 h60
  text "1" at 13266.96,2439.58 h60
  text "3" at 13935.96,2439.58 h60
  text "X" at 12507.97,2293.39 h60
  text "RoHS" at 12635.96,2293.39 h60
  text "OTHER" at 13280.36,2293.39 h60
  text "PER ORDER" at 13677.42,2293.39 h60
  text "ALL BOARDS MUST MEET OR EXCEED UL94-V0 REQUIREMENTS." at 11361,2139.57 h60
  text "PCB MUST BEAR THE UL94V-0 UL REGISTERED MATERIAL ID NUMBER" at 11361,2023.5 h60
  text "ADDITIONAL REQUIREMENTS:" at 11333.46,1854.08 h60
  text "MICROSECTION:" at 11408.23,1746.95 h60
  text "YES" at 12313.96,1746.95 h60
  text "REQUIRED" at 13175.46,1602.62 h60
  text "BARE BOARD ELEC. TEST:" at 11408.23,1599.76 h60
  text "NONE" at 12713.96,1599.76 h60
  text "X" at 13057.46,1599.76 h60
  text "PER ORDER" at 13767.46,1599.76 h60
  text "XX MIL VIAS REQUIRE NON-CONDUCTIVE FILL AND PLANARIZE" at 11576.38,1394.82 h59
  text "XX MIL VIAS REQUIRE CONDUCTIVE FILL AND PLANARIZE" at 11584.38,1290.84 h60
  text "OUTER XX MIL TRACES REQUIRE 50 OHM SINGLE-ENDED IMPEDANCE" at 11583.39,1127.46 h58
  text "LAYER 2 & 3 (INNER LAYERS) XX MIL WIDE, XX MIL SPACE / TRACES REQUIRE 100 OHM DIFFERENTIAL IMPEDANCE" at 11575.39,891.74 h60
  text ".Layer_Name" at 577,-858.49 h60
M11 Gerber Information:
  lines w10: -292,-930.17 6308,-930.17 ; -292,-726.83 6310,-726.83 ; -292,-523.5 -292,-1133.5 3713,-1133.5 6310,-1133.5 6310,-523.5 -291.5,-523.5 -291.5,-1133.5 1284,-1133.5 ; 2173,-1133.5 2173,-523.5 ; 3440,-726.83 3440,-523.5 ; 4280,-726.83 4280,-523.5 ; 4902,-1140 4902,-937.17
  text "ALL ARTWORK VIEWED FROM TOP SIDE" at -228.5,-655.67 h60
  text "BOARD #:" at 2248,-655.67 h60
  text ".PRJ_Number" at 2793.5,-655.67 h60
  text "REV:" at 3638,-655.67 h60
  text ".PCB_Rev" at 3929.5,-655.67 h60
  text "SVN REV:" at 4476,-655.67 h60
  text ".VersionControl_RevNumber" at 4982,-655.67 h60
  text "LAYER NAME =" at -228.5,-858.49 h60
  text "TID #:" at 2248,-859 h60
  text ".TID" at 2793.5,-859 h60
  text "PLOT NAME =" at -228.5,-1064.34 h60
  text ".plot_File_Name" at 577,-1064.34 h60
  text "GENERATED    :" at 2250,-1064.34 h60
  text ".Print_Date" at 3119.5,-1064.34 h60
  text ".Print_Time" at 3848.5,-1064.34 h60
  text "TEXAS INSTRUMENTS" at 5113,-1064.34 h60
M12 Stackup:
  drawing of 295 lines, arcs and shapes, not listed
  text "Layer" at 9322.5,7842.5 h60
  text "Name" at 9732.41,7842.5 h60
  text "Material" at 11142,7842.5 h60
  text "Thickness" at 12001.77,7842.5 h60
  text "Constant" at 12651.6,7842.5 h60
  text "Board Layer Stack" at 13221.47,7842.5 h60
  text "1" at 9322.5,7722.5 h60
  text "Top Overlay" at 9732.41,7722.5 h60
  text "2" at 9322.5,7602.5 h60
  text "Top Solder" at 9732.41,7602.5 h60
  text "Solder Resist" at 11142,7602.5 h60
  text "0.40mil" at 12001.77,7602.5 h60
  text "3.5" at 12651.6,7602.5 h60
  text "3" at 9322.5,7482.5 h60
  text "Layer 1 - Top Layer" at 9732.41,7482.5 h60
  text "Copper" at 11142,7482.5 h60
  text "2.80mil" at 12001.77,7482.5 h60
  text "4" at 9322.5,7362.5 h60
  text "Dielectric 1" at 9732.41,7362.5 h60
  text "FR-4 High Tg" at 11142,7362.5 h60
  text "6.00mil" at 12001.77,7362.5 h60
  text "4.2" at 12651.6,7362.5 h60
  text "5" at 9322.5,7242.5 h60
  text "Layer 2 - GND" at 9732.41,7242.5 h60
  text "Copper" at 11142,7242.5 h60
  text "1.40mil" at 12001.77,7242.5 h60
  text "6" at 9322.5,7122.5 h60
  text "Dielectric 2" at 9732.41,7122.5 h60
  text "FR-4 High Tg" at 11142,7122.5 h60
  text "41.00mil" at 12001.77,7122.5 h60
  text "4.2" at 12651.6,7122.5 h60
  text "7" at 9322.5,7002.5 h60
  text "Layer 3 - Signal" at 9732.41,7002.5 h60
  text "Copper" at 11142,7002.5 h60
  text "1.40mil" at 12001.77,7002.5 h60
  text "8" at 9322.5,6882.5 h60
  text "Dielectric 3" at 9732.41,6882.5 h60
  text "FR-4 High Tg" at 11142,6882.5 h60
  text "6.00mil" at 12001.77,6882.5 h60
  text "4.2" at 12651.6,6882.5 h60
  text "9" at 9322.5,6762.5 h60
  text "Layer 4 - Bottom Layer" at 9732.41,6762.5 h60
  text "Copper" at 11142,6762.5 h60
  text "2.80mil" at 12001.77,6762.5 h60
  text "10" at 9322.5,6642.5 h60
  text "Bottom Solder" at 9732.41,6642.5 h60
  text "Solder Resist" at 11142,6642.5 h60
  text "0.40mil" at 12001.77,6642.5 h60
  text "3.5" at 12651.6,6642.5 h60
  text "11" at 9322.5,6522.5 h60
  text "Bottom Overlay" at 9732.41,6522.5 h60
  text ".Layer_Name" at 577,-858.49 h60
M13 Component Bodies Top:
  text ".Layer_Name" at 577,-858.49 h60
M14 Component Bodies Bottom:
  text ".Layer_Name" at 577,-858.49 h60
M15 Courtyards Top:
  text ".Layer_Name" at 577,-858.49 h60
M16 Courtyards Bottom:
  text ".Layer_Name" at 577,-858.49 h60
Drill Drawing:
  circle w10: c5270.22,1086.98 r16.58
  circle w10: c5270.22,1086.98 r27.63
  circle w10: c5270.22,216.74 r27.63
  lines w10: 5242.59,313.44 5297.84,313.44 5297.84,368.69 5242.59,368.69 5242.59,313.44 ; 5242.59,451.57 5256.4,451.57 5270.22,437.76 5284.03,451.57 5297.84,451.57 5284.03,465.38 5297.84,479.2 5284.03,479.2 5270.22,493.01 5256.4,479.2 5242.59,479.2 5256.4,465.38 5242.59,451.57 ; 5242.59,686.4 5297.84,686.4 5297.84,741.65 5242.59,741.65 5242.59,686.4 ; 5242.59,810.72 5242.59,824.53 5256.4,838.34 5242.59,852.16 5242.59,865.97 5256.4,865.97 5270.22,852.16 5284.03,865.97 5297.84,865.97 5297.84,852.16 5284.03,838.34 5297.84,824.53 5297.84,810.72 5284.03,810.72 5270.22,824.53 5256.4,810.72 5242.59,810.72 ; 5242.59,935.04 5270.22,948.85 5297.84,935.04 5284.03,962.66 5297.84,990.29 5270.22,976.48 5242.59,990.29 5256.4,962.66 5242.59,935.04 ; 5242.59,1197.49 5256.4,1197.49 5270.22,1183.68 5284.03,1197.49 5297.84,1197.49 5284.03,1211.3 5297.84,1225.12 5284.03,1225.12 5270.22,1238.93 5256.4,1225.12 5242.59,1225.12 5256.4,1211.3 5242.59,1197.49 ; 5242.59,1308 5270.22,1321.81 5297.84,1308 5284.03,1335.62 5297.84,1363.25 5270.22,1349.44 5242.59,1363.25 5256.4,1335.62 5242.59,1308 ; 5242.59,1459.94 5270.22,1432.32 5297.84,1459.94 5270.22,1487.57 5242.59,1459.94 ; 5253.64,457.09 5261.93,457.09 5270.22,448.81 5278.51,457.09 5286.79,457.09 5278.51,465.38 5286.79,473.67 5278.51,473.67 5270.22,481.96 5261.93,473.67 5253.64,473.67 5261.93,465.38 5253.64,457.09 ; 5253.64,697.45 5286.79,697.45 5286.79,730.6 5253.64,730.6 5253.64,697.45 ; 5253.64,1319.05 5270.22,1327.33 5286.79,1319.05 5278.51,1335.62 5286.79,1352.2 5270.22,1343.91 5253.64,1352.2 5261.93,1335.62 5253.64,1319.05
  lines w15: 5192.5,151.82 8959.42,151.82 ; 5192.5,1519.34 8959.42,1519.34 ; 5530.36,27.5 5530.36,1643.66 ; 5831.62,27.5 5831.62,1643.66 ; 6394.89,27.5 6394.89,1643.66 ; 6654.03,27.5 6654.03,1643.66 ; 7029.18,27.5 7029.18,1643.66 ; 8222.16,27.5 8222.16,1643.66 ; 8525.45,27.5 8525.45,1643.66 ; 5192.5,27.5 8959.42,27.5 8959.42,1643.66 5192.5,1643.66 5192.5,27.5
  text "Symbol" at 5267.09,1556.64 h72
  text "Count" at 5567.66,1556.64 h72
  text "Hole Size" at 5868.91,1556.64 h72
  text "Plated" at 6432.18,1556.64 h72
  text "Hole Type" at 6691.32,1556.64 h72
  text "Drill Layer Pair" at 7066.48,1556.64 h72
  text "Via/Pad" at 8259.45,1556.64 h72
  text "Pad Shape" at 8562.75,1556.64 h72
  text "2" at 5567.66,1432.32 h60
  text "31.50mil (0.800mm)" at 5868.91,1432.32 h60
  text "NPTH" at 6432.18,1432.32 h60
  text "Round" at 6691.32,1432.32 h60
  text "Layer 1 - Top Layer - Layer 4 - Bottom Layer" at 7066.48,1432.32 h60
  text "Pad" at 8259.45,1432.32 h60
  text "Rounded" at 8562.75,1432.32 h60
  text "2" at 5567.66,1308 h60
  text "45.28mil (1.150mm)" at 5868.91,1308 h60
  text "PTH" at 6432.18,1308 h60
  text "Round" at 6691.32,1308 h60
  text "Layer 1 - Top Layer - Layer 4 - Bottom Layer" at 7066.48,1308 h60
  text "Pad" at 8259.45,1308 h60
  text "(Mixed)" at 8562.75,1308 h60
  text "2" at 5567.66,1183.68 h60
  text "50.00mil (1.270mm)" at 5868.91,1183.68 h60
  text "PTH" at 6432.18,1183.68 h60
  text "Round" at 6691.32,1183.68 h60
  text "Layer 1 - Top Layer - Layer 4 - Bottom Layer" at 7066.48,1183.68 h60
  text "Pad" at 8259.45,1183.68 h60
  text "(Mixed)" at 8562.75,1183.68 h60
  text "4" at 5567.66,1059.36 h60
  text "35.00mil (0.889mm)" at 5868.91,1059.36 h60
  text "PTH" at 6432.18,1059.36 h60
  text "Round" at 6691.32,1059.36 h60
  text "Layer 1 - Top Layer - Layer 4 - Bottom Layer" at 7066.48,1059.36 h60
  text "Pad" at 8259.45,1059.36 h60
  text "(Mixed)" at 8562.75,1059.36 h60
  text "8" at 5567.66,935.04 h60
  text "40.16mil (1.020mm)" at 5868.91,935.04 h60
  text "PTH" at 6432.18,935.04 h60
  text "Round" at 6691.32,935.04 h60
  text "Layer 1 - Top Layer - Layer 4 - Bottom Layer" at 7066.48,935.04 h60
  text "Pad" at 8259.45,935.04 h60
  text "(Mixed)" at 8562.75,935.04 h60
  text "8" at 5567.66,810.72 h60
  text "63.00mil (1.600mm)" at 5868.91,810.72 h60
  text "PTH" at 6432.18,810.72 h60
  text "Round" at 6691.32,810.72 h60
  text "Layer 1 - Top Layer - Layer 4 - Bottom Layer" at 7066.48,810.72 h60
  text "Pad" at 8259.45,810.72 h60
  text "Rounded" at 8562.75,810.72 h60
  text "10" at 5567.66,686.4 h60
  text "25.00mil (0.635mm)" at 5868.91,686.4 h60
  text "PTH" at 6432.18,686.4 h60
  text "Round" at 6691.32,686.4 h60
  text "Layer 1 - Top Layer - Layer 4 - Bottom Layer" at 7066.48,686.4 h60
  text "Pad" at 8259.45,686.4 h60
  text "Rounded" at 8562.75,686.4 h60
  text "21" at 5567.66,562.08 h60
  text "43.31mil (1.100mm)" at 5868.91,562.08 h60
  text "PTH" at 6432.18,562.08 h60
  text "Round" at 6691.32,562.08 h60
  text "Layer 1 - Top Layer - Layer 4 - Bottom Layer" at 7066.48,562.08 h60
  text "Pad" at 8259.45,562.08 h60
  text "(Mixed)" at 8562.75,562.08 h60
  text "B" at 5241.81,552.09 h55.25
  text "32" at 5567.66,437.76 h60
  text "7.87mil (0.200mm)" at 5868.91,437.76 h60
  text "PTH" at 6432.18,437.76 h60
  text "Round" at 6691.32,437.76 h60
  text "Layer 1 - Top Layer - Layer 4 - Bottom Layer" at 7066.48,437.76 h60
  text "Via" at 8259.45,437.76 h60
  text "Rounded" at 8562.75,437.76 h60
  text "109" at 5567.66,313.44 h60
  text "40.00mil (1.016mm)" at 5868.91,313.44 h60
  text "PTH" at 6432.18,313.44 h60
  text "Round" at 6691.32,313.44 h60
  text "Layer 1 - Top Layer - Layer 4 - Bottom Layer" at 7066.48,313.44 h60
  text "Pad" at 8259.45,313.44 h60
  text "(Mixed)" at 8562.75,313.44 h60
  text "376" at 5567.66,189.12 h60
  text "10.00mil (0.254mm)" at 5868.91,189.12 h60
  text "PTH" at 6432.18,189.12 h60
  text "Round" at 6691.32,189.12 h60
  text "Layer 1 - Top Layer - Layer 4 - Bottom Layer" at 7066.48,189.12 h60
  text "Via" at 8259.45,189.12 h60
  text "Rounded" at 8562.75,189.12 h60
  text "574 Total" at 5567.66,64.8 h60
  text ".Layer_Name" at 577,-858.49 h60
M17 Embedded Cavity:
  text ".Layer_Name" at 577,-858.49 h60
M18 Embedded Assembly:
  text ".Layer_Name" at 577,-858.49 h60
M19 Embedded Keepout:
  text ".Layer_Name" at 577,-858.49 h60

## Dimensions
0,0 to 0,4000 on M2 Board Dimensions
0,0 to 4950,0 on M2 Board Dimensions
0,-400 to 1000,-400 on M2 Board Dimensions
